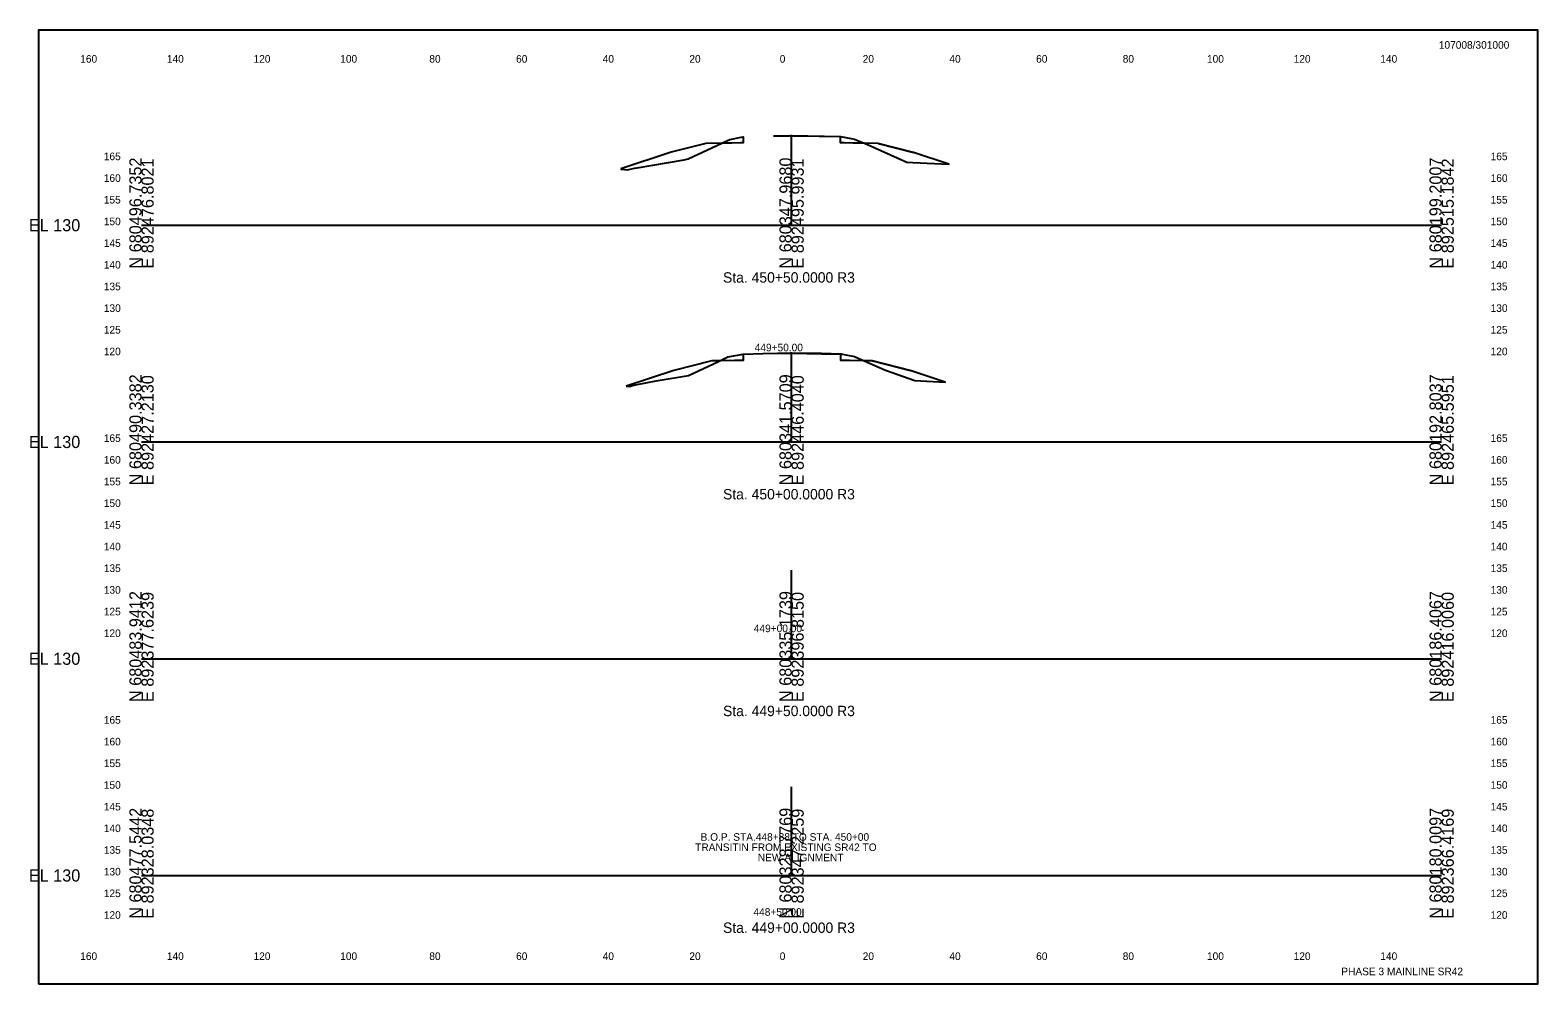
# Model space of a CAD drawing. Extents: x 21059 to 22955, y 6470 to 17494.
# Drawn here: x 21469.1 to 21817, y 6699.8 to 6919.8 of the extents above; entities that cross this region are included whole.
import ezdxf

# ---------------------------------------------------------------- set-up
doc = ezdxf.new("R2010")
doc.units = 0
for name, color, linetype in [('Draft_XS_Grid', 7, 'Continuous'), ('Draft_XS_Text', 7, 'Continuous'), ('DTM CONTOURS_MAJOR', 7, 'Continuous'), ('DTM_TEMP_DROP', 7, 'Continuous'), ('SLOPE_STAKES_FILL', 7, 'Continuous'), ('X_PROFILES_1', 7, 'Continuous'), ('XS_P_SUBGRADE_LEVELING', 7, 'Continuous'), ('XS_P_TX_CLEARZONE', 7, 'Continuous'), ('XS_SHEET_EW_TX_VOLUME', 7, 'Continuous')]:
    doc.layers.add(name, color=color, linetype=linetype)

msp = doc.modelspace()

# ---------------------------------------------------------------- linework, layer by layer
at = {"layer": 'DTM CONTOURS_MAJOR'}
for p, q in [((21644.84, 6874.84), (21644.84, 6895.69)), ((21494.84, 6874.84), (21644.84, 6874.84)), ((21644.84, 6874.84), (21794.84, 6874.84)), ((21644.84, 6824.84), (21644.84, 6845.52)), ((21494.84, 6824.84), (21644.84, 6824.84)), ((21644.84, 6824.84), (21794.84, 6824.84)), ((21644.84, 6774.84), (21644.84, 6795.3)), ((21494.84, 6774.84), (21644.84, 6774.84)), ((21644.84, 6774.84), (21794.84, 6774.84)), ((21644.84, 6724.84), (21644.84, 6745.25)), ((21494.84, 6724.84), (21644.84, 6724.84)), ((21644.84, 6724.84), (21794.84, 6724.84))]:
    msp.add_line(p, q, dxfattribs=at)
at = {"layer": 'DTM_TEMP_DROP'}
msp.add_lwpolyline([(21471.04, 6699.84), (21817.04, 6699.84), (21817.04, 6919.84), (21471.04, 6919.84)], close=True, dxfattribs=at)
at = {"layer": 'XS_P_TX_CLEARZONE'}
for points in [[(21625.07, 6893.68), (21617.03, 6891.67)], [(21664.8, 6893.67), (21672.96, 6891.63)], [(21626.44, 6843.53), (21617.64, 6841.33)], [(21663.5, 6843.52), (21672.18, 6841.35)]]:
    msp.add_lwpolyline(points, dxfattribs=at)
at = {"layer": 'XS_SHEET_EW_TX_VOLUME'}
for points in [[(21640.64, 6895.36), (21643.66, 6895.44), (21644.95, 6895.49), (21646.27, 6895.48), (21656.15, 6895.31), (21658.99, 6894.77), (21659.32, 6894.71), (21660.85, 6894.08), (21661.63, 6893.74), (21658.96, 6893.79), (21656.96, 6893.83), (21656.15, 6893.85), (21656.15, 6894.6), (21656.15, 6895.22), (21644.84, 6895.45)], [(21605.46, 6887.81), (21605.59, 6887.74), (21606.98, 6887.65), (21607.32, 6887.67), (21608.57, 6888.01), (21609.23, 6888.08), (21620.06, 6889.93), (21620.99, 6890.12), (21628.74, 6893.75), (21625.07, 6893.68), (21617.03, 6891.67)], [(21628.74, 6893.75), (21629.37, 6894.05), (21630.6, 6894.61), (21633.17, 6895.12), (21633.67, 6895.2), (21633.67, 6894.6), (21633.67, 6893.85), (21633.03, 6893.84), (21631.03, 6893.8)], [(21661.63, 6893.74), (21671.45, 6889.41), (21672.82, 6889.32), (21681.15, 6888.9), (21672.96, 6891.63), (21664.8, 6893.67)], [(21606.69, 6837.68), (21607.53, 6837.62), (21607.93, 6837.8), (21608.81, 6838.05), (21613.56, 6838.92), (21621.08, 6840.2), (21626.79, 6842.88), (21628.25, 6843.56), (21626.44, 6843.53), (21617.64, 6841.33)], [(21628.25, 6843.56), (21630.14, 6844.45), (21631.87, 6844.77), (21633.64, 6845.12), (21638.23, 6845.24), (21645, 6845.4), (21651.72, 6845.29), (21656.18, 6845.15), (21657.39, 6844.94), (21659.32, 6844.57), (21661.61, 6843.56), (21658.18, 6843.63), (21656.18, 6843.67), (21656.18, 6844.42), (21656.18, 6845.04), (21651.72, 6845.13), (21645, 6845.27), (21644.84, 6845.27), (21638.23, 6845.14), (21633.64, 6845.05), (21633.64, 6844.42), (21633.64, 6843.67), (21631.64, 6843.63)], [(21661.61, 6843.56), (21666.48, 6841.41), (21673.3, 6839.01), (21680.25, 6838.66), (21672.18, 6841.35), (21663.5, 6843.52)]]:
    msp.add_lwpolyline(points, close=True, dxfattribs=at)

# ---------------------------------------------------------------- texts
at = {"layer": 'Draft_XS_Grid'}
for s, p in [('  165  ', (21484.84, 6889.84)), ('  165  ', (21804.84, 6889.84)), ('  160  ', (21484.84, 6884.84)), ('  160  ', (21804.84, 6884.84)), ('  155  ', (21484.84, 6879.84)), ('  155  ', (21804.84, 6879.84)), ('  150  ', (21484.84, 6874.84)), ('  150  ', (21804.84, 6874.84)), ('  145  ', (21484.84, 6869.84)), ('  145  ', (21804.84, 6869.84)), ('  140  ', (21484.84, 6864.84)), ('  140  ', (21804.84, 6864.84)), ('  135  ', (21484.84, 6859.84)), ('  135  ', (21804.84, 6859.84)), ('  130  ', (21484.84, 6854.84)), ('  130  ', (21804.84, 6854.84)), ('  125  ', (21484.84, 6849.84)), ('  125  ', (21804.84, 6849.84)), ('  120  ', (21484.84, 6844.84)), ('  120  ', (21804.84, 6844.84)), ('  165  ', (21484.84, 6824.84)), ('  165  ', (21804.84, 6824.84)), ('  160  ', (21484.84, 6819.84)), ('  160  ', (21804.84, 6819.84)), ('  155  ', (21484.84, 6814.84)), ('  155  ', (21804.84, 6814.84)), ('  150  ', (21484.84, 6809.84)), ('  150  ', (21804.84, 6809.84)), ('  145  ', (21484.84, 6804.84)), ('  145  ', (21804.84, 6804.84)), ('  140  ', (21484.84, 6799.84)), ('  140  ', (21804.84, 6799.84)), ('  135  ', (21484.84, 6794.84)), ('  135  ', (21804.84, 6794.84)), ('  130  ', (21484.84, 6789.84)), ('  130  ', (21804.84, 6789.84)), ('  125  ', (21484.84, 6784.84)), ('  125  ', (21804.84, 6784.84)), ('  120  ', (21484.84, 6779.84)), ('  120  ', (21804.84, 6779.84)), ('  165  ', (21484.84, 6759.84)), ('  165  ', (21804.84, 6759.84)), ('  160  ', (21484.84, 6754.84)), ('  160  ', (21804.84, 6754.84)), ('  155  ', (21484.84, 6749.84)), ('  155  ', (21804.84, 6749.84)), ('  150  ', (21484.84, 6744.84)), ('  150  ', (21804.84, 6744.84)), ('  145  ', (21484.84, 6739.84)), ('  145  ', (21804.84, 6739.84)), ('  140  ', (21484.84, 6734.84)), ('  140  ', (21804.84, 6734.84)), ('  135  ', (21484.84, 6729.84)), ('  135  ', (21804.84, 6729.84)), ('  130  ', (21484.84, 6724.84)), ('  130  ', (21804.84, 6724.84)), ('  125  ', (21484.84, 6719.84)), ('  125  ', (21804.84, 6719.84)), ('  120  ', (21484.84, 6714.84)), ('  120  ', (21804.84, 6714.84))]:
    msp.add_text(s, height=1.75, dxfattribs=at).set_placement(p)
at = {"layer": 'Draft_XS_Text'}
for s, p in [('107008/301000', (21794.19, 6915.55)), ('  160  ', (21479.4, 6912.34)), ('  140  ', (21499.39, 6912.34)), ('  120  ', (21519.39, 6912.34)), ('  100  ', (21539.39, 6912.34)), ('  80  ', (21559.95, 6912.34)), ('  60  ', (21579.97, 6912.34)), ('  40  ', (21599.95, 6912.34)), ('  20  ', (21619.95, 6912.34)), ('  0  ', (21640.81, 6912.34)), ('  0  ', (21640.81, 6912.34)), ('  20  ', (21659.95, 6912.34)), ('  40  ', (21679.95, 6912.34)), ('  60  ', (21699.97, 6912.34)), ('  80  ', (21719.95, 6912.34)), ('  100  ', (21739.39, 6912.34)), ('  120  ', (21759.39, 6912.34)), ('  140  ', (21779.39, 6912.34)), ('  160  ', (21479.4, 6705.34)), ('  140  ', (21499.39, 6705.34)), ('  120  ', (21519.39, 6705.34)), ('  100  ', (21539.39, 6705.34)), ('  80  ', (21559.95, 6705.34)), ('  60  ', (21579.97, 6705.34)), ('  40  ', (21599.95, 6705.34)), ('  20  ', (21619.95, 6705.34)), ('  0  ', (21640.81, 6705.34)), ('  0  ', (21640.81, 6705.34)), ('  20  ', (21659.95, 6705.34)), ('  40  ', (21679.95, 6705.34)), ('  60  ', (21699.97, 6705.34)), ('  80  ', (21719.95, 6705.34)), ('  100  ', (21739.39, 6705.34)), ('  120  ', (21759.39, 6705.34)), ('  140  ', (21779.39, 6705.34)), ('PHASE 3 MAINLINE SR42', (21771.68, 6701.82))]:
    msp.add_text(s, height=1.75, dxfattribs=at).set_placement(p)
at = {"layer": 'DTM CONTOURS_MAJOR'}
for s, p in [('N 680496.7352', (21494.84, 6864.84)), ('E 892476.8021', (21497.64, 6864.84)), ('N 680347.9680', (21644.84, 6864.84)), ('E 892495.9931', (21647.64, 6864.84)), ('N 680199.2007', (21794.84, 6864.84)), ('E 892515.1842', (21797.64, 6864.84)), ('N 680490.3382', (21494.84, 6814.84)), ('E 892427.2130', (21497.64, 6814.84)), ('N 680341.5709', (21644.84, 6814.84)), ('E 892446.4040', (21647.64, 6814.84)), ('N 680192.8037', (21794.84, 6814.84)), ('E 892465.5951', (21797.64, 6814.84)), ('N 680483.9412', (21494.84, 6764.84)), ('E 892377.6239', (21497.64, 6764.84)), ('N 680335.1739', (21644.84, 6764.84)), ('E 892396.8150', (21647.64, 6764.84)), ('N 680186.4067', (21794.84, 6764.84)), ('E 892416.0060', (21797.64, 6764.84)), ('N 680477.5442', (21494.84, 6714.84)), ('E 892328.0348', (21497.64, 6714.84)), ('N 680328.7769', (21644.84, 6714.84)), ('E 892347.2259', (21647.64, 6714.84)), ('N 680180.0097', (21794.84, 6714.84)), ('E 892366.4169', (21797.64, 6714.84))]:
    msp.add_text(s, height=2.8, rotation=90, dxfattribs=at).set_placement(p)
for p in [(21468.84, 6873.44), (21468.84, 6823.44), (21468.84, 6773.44), (21468.84, 6723.44)]:
    msp.add_text('EL 130', height=2.8, dxfattribs=at).set_placement(p)
at = {"layer": 'SLOPE_STAKES_FILL'}
for s, p in [('  449+50.00  ', (21635.03, 6845.75)), ('  449+00.00  ', (21634.82, 6780.96)), ('TRANSITIN FROM EXISTING SR42 TO ', (21622.6, 6730.47)), ('B.O.P. STA.448+88 TO STA. 450+00', (21623.84, 6732.84)), ('NEW ALIGNMENT', (21637.05, 6728.1)), ('  448+50.00  ', (21634.74, 6715.54))]:
    msp.add_text(s, height=1.75, dxfattribs=at).set_placement(p)
at = {"layer": 'X_PROFILES_1'}
for s, p in [('Sta. 450+50.0000 R3', (21629.02, 6861.59)), ('Sta. 450+00.0000 R3', (21629.02, 6811.59)), ('Sta. 449+50.0000 R3', (21629.02, 6761.59)), ('Sta. 449+00.0000 R3', (21629.02, 6711.59))]:
    msp.add_text(s, height=2.4, dxfattribs=at).set_placement(p)
at = {"layer": 'XS_P_SUBGRADE_LEVELING'}
for p in [(21681.11, 6888.84), (21605.43, 6887.75), (21606.65, 6837.62), (21680.21, 6838.6)]:
    msp.add_text('X', height=0.12, dxfattribs=at).set_placement(p)

doc.saveas('drawing.dxf')
